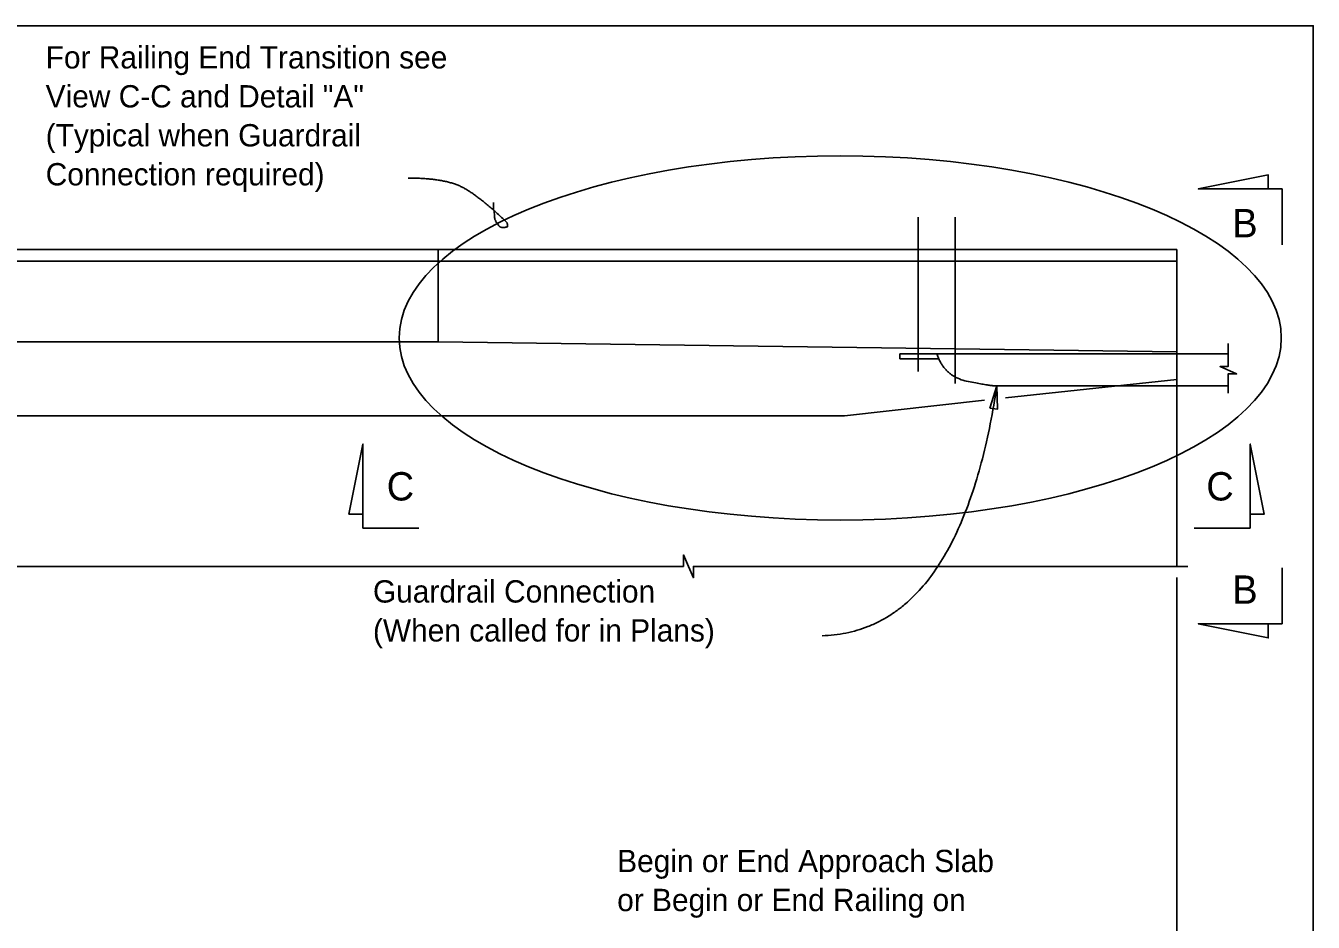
# Model space of a CAD drawing. Extents: x 0 to 41.1, y 0 to 25.9.
# Drawn here: x 29.43 to 41.05, y 17.85 to 25.95 of the extents above; entities that cross this region are included whole.
import ezdxf

# ---------------------------------------------------------------- set-up
doc = ezdxf.new("R2010")
doc.units = 0
for name, color, linetype in [('ActivePts-ConstElements', 7, 'Continuous'), ('Dimension', 7, 'Continuous'), ('Miscellaneous', 7, 'Continuous'), ('Miscellaneous1', 7, 'Continuous'), ('TextStructures', 7, 'Continuous'), ('TrafBarrierConc', 7, 'Continuous')]:
    doc.layers.add(name, color=color, linetype=linetype)

msp = doc.modelspace()

# ---------------------------------------------------------------- linework, layer by layer
at = {"layer": 'ActivePts-ConstElements'}
msp.add_lwpolyline([(0, 0), (41.051, 0), (41.051, 25.946), (0, 25.946)], close=True, dxfattribs=at)
at = {"layer": 'Dimension'}
for p, q in [((40.012, 24.472), (40.644, 24.599)), ((40.644, 24.599), (40.644, 24.472)), ((40.771, 24.472), (40.012, 24.472)), ((40.771, 23.966), (40.771, 24.472)), ((37.484, 24.216), (37.484, 22.822)), ((37.818, 24.216), (37.818, 22.716)), ((32.47, 22.167), (32.344, 21.535)), ((32.47, 21.408), (32.47, 22.167)), ((40.482, 21.408), (40.482, 22.167)), ((40.482, 22.167), (40.608, 21.535)), ((32.344, 21.535), (32.47, 21.535)), ((40.608, 21.535), (40.482, 21.535)), ((32.976, 21.408), (32.47, 21.408)), ((39.975, 21.408), (40.482, 21.408)), ((40.771, 21.05), (40.771, 20.544)), ((39.818, 20.252), (39.818, 20.963)), ((39.818, 14.555), (39.818, 20.963)), ((40.771, 20.544), (40.012, 20.544)), ((40.012, 20.544), (40.644, 20.417)), ((40.644, 20.417), (40.644, 20.544))]:
    msp.add_line(p, q, dxfattribs=at)
for points in [[(40.644, 24.472), (40.644, 24.599), (40.012, 24.472)], [(38.13, 22.492), (38.195, 22.693), (38.199, 22.482)], [(32.47, 21.535), (32.344, 21.535), (32.47, 22.167)], [(40.482, 21.535), (40.608, 21.535), (40.482, 22.167)], [(40.644, 20.544), (40.644, 20.417), (40.012, 20.544)]]:
    msp.add_lwpolyline(points, close=True, dxfattribs=at)
for points in [[(33.772, 24.167), (33.772, 24.155), (33.776, 24.155), (33.776, 24.151), (33.776, 24.147), (33.776, 24.143), (33.776, 24.139), (33.776, 24.135), (33.776, 24.131), (33.772, 24.131), (33.768, 24.131), (33.768, 24.128), (33.764, 24.128), (33.76, 24.128), (33.756, 24.128), (33.756, 24.124), (33.752, 24.124), (33.749, 24.124), (33.745, 24.124), (33.741, 24.124), (33.737, 24.124), (33.733, 24.124), (33.729, 24.124), (33.725, 24.124), (33.721, 24.124), (33.717, 24.128), (33.713, 24.128), (33.709, 24.131), (33.705, 24.131), (33.701, 24.135), (33.697, 24.139), (33.697, 24.143), (33.693, 24.143), (33.693, 24.147), (33.689, 24.151), (33.689, 24.155), (33.685, 24.155), (33.685, 24.159), (33.681, 24.159), (33.681, 24.163), (33.681, 24.167), (33.677, 24.167), (33.677, 24.171), (33.673, 24.171), (33.673, 24.175), (33.67, 24.179), (33.67, 24.183), (33.666, 24.183), (33.666, 24.187), (33.666, 24.191), (33.662, 24.195), (33.662, 24.199), (33.662, 24.203), (33.662, 24.207), (33.662, 24.211), (33.658, 24.211), (33.658, 24.214), (33.658, 24.218), (33.658, 24.222), (33.658, 24.226), (33.658, 24.23), (33.658, 24.234), (33.658, 24.242), (33.654, 24.258), (33.654, 24.266), (33.654, 24.27), (33.654, 24.278), (33.65, 24.282), (33.65, 24.286), (33.65, 24.29), (33.65, 24.294), (33.65, 24.297), (33.65, 24.301), (33.65, 24.305), (33.65, 24.309), (33.65, 24.317), (33.65, 24.325), (33.65, 24.329), (33.65, 24.337), (33.65, 24.341), (33.65, 24.345), (33.65, 24.349), (33.65, 24.349)], [(40.281, 22.627), (40.281, 22.802), (40.359, 22.802), (40.209, 22.868), (40.281, 22.868), (40.281, 23.075)], [(23.737, 21.063), (24.629, 21.063), (24.629, 21.167), (24.674, 21.063), (24.719, 20.96), (24.719, 21.063), (30.61, 21.063)], [(30.61, 21.063), (35.364, 21.063), (35.364, 21.167), (35.409, 21.063), (35.454, 20.96), (35.454, 21.063), (39.919, 21.063)]]:
    msp.add_lwpolyline(points, dxfattribs=at)
msp.add_ellipse((36.78, 23.126), major_axis=(-3.982, 0), ratio=0.412977, dxfattribs=at)
for points in [[(32.88, 24.57), (33.211, 24.57), (33.527, 24.404), (33.772, 24.167)], [(38.195, 22.693), (37.858, 20.475), (36.617, 20.436)]]:
    msp.add_open_spline(points, degree=2, dxfattribs=at)
at = {"layer": 'Miscellaneous'}
for p, q in [((37.318, 22.984), (40.281, 22.984)), ((37.318, 22.938), (37.318, 22.984)), ((37.66, 22.938), (37.318, 22.938)), ((38.195, 22.693), (40.281, 22.693))]:
    msp.add_line(p, q, dxfattribs=at)
msp.add_open_spline([(37.651, 22.984), (37.721, 22.772), (38.161, 22.69), (38.195, 22.693)], degree=2, dxfattribs=at)
at = {"layer": 'Miscellaneous1'}
msp.add_lwpolyline([(0, 25.946), (41.051, 25.946), (41.051, 0), (0, 0)], close=True, dxfattribs=at)
at = {"layer": 'TrafBarrierConc'}
for p, q in [((23.837, 23.924), (39.818, 23.924)), ((33.151, 23.924), (33.151, 23.091)), ((39.818, 23.924), (39.818, 21.063)), ((23.837, 23.82), (33.151, 23.82)), ((33.151, 23.82), (39.818, 23.82)), ((23.837, 23.091), (33.151, 23.091)), ((33.151, 23.091), (39.818, 23)), ((38.273, 22.586), (39.818, 22.75)), ((36.818, 22.424), (38.082, 22.564)), ((23.837, 22.424), (36.818, 22.424))]:
    msp.add_line(p, q, dxfattribs=at)

# ---------------------------------------------------------------- texts
at = {"layer": 'Dimension'}
for s, p in [('For Railing End Transition see ', (29.606, 25.56)), ('View C-C and Detail "A" ', (29.606, 25.208)), ('(Typical when Guardrail', (29.606, 24.856)), ('Connection required)', (29.606, 24.504)), ('Guardrail Connection', (32.561, 20.736)), ('(When called for in Plans)', (32.561, 20.384)), ('Begin or End Approach Slab ', (34.766, 18.301)), ('or Begin or End Railing on ', (34.766, 17.949))]:
    msp.add_text(s, height=0.2016, dxfattribs=at).set_placement(p)
at = {"layer": 'TextStructures'}
for s, p in [('B', (40.32, 24.035)), ('C', (32.685, 21.658)), ('C', (40.085, 21.658)), ('B', (40.32, 20.725))]:
    msp.add_text(s, height=0.256, dxfattribs=at).set_placement(p)

doc.saveas('drawing.dxf')
